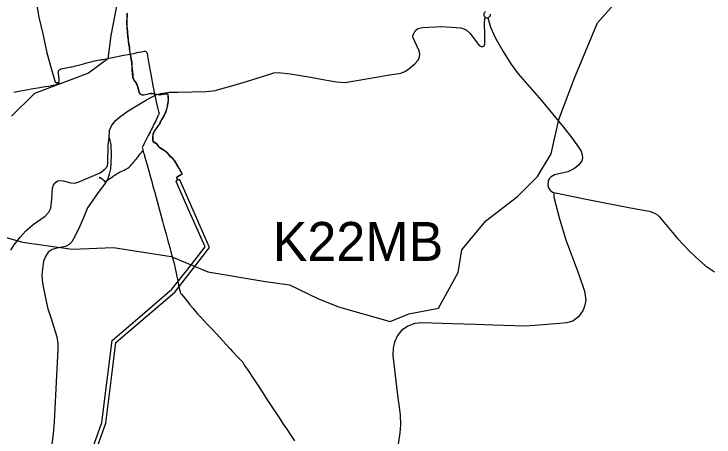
# Model space of a CAD drawing. Extents: x -789162 to -606354, y -1062736 to -945481.
# Drawn here: x -681766 to -679066, y -983825 to -982196 of the extents above; entities that cross this region are included whole.
import ezdxf

# ---------------------------------------------------------------- set-up
doc = ezdxf.new("R2010")
doc.units = 0
for name, color, linetype in [('_SIRSI VZTAHY_ELEKTRICKE VEDENI VN 110 kV S', 7, 'Continuous'), ('_SIRSI VZTAHY_SILNICE II TRIDY_STAV', 7, 'Continuous'), ('_SIRSI VZTAHY_SILNICE III TRIDY_STAV', 7, 'Continuous'), ('_SIRSI VZTAHY_USES_NRBK_S', 7, 'Continuous'), ('_SIRSI VZTAHY_USES_popis S', 7, 'Continuous'), ('_SIRSI VZTAHY_VTL PLYNOVOD', 7, 'Continuous')]:
    doc.layers.add(name, color=color, linetype=linetype)

msp = doc.modelspace()

# ---------------------------------------------------------------- linework, layer by layer
at = {"layer": '_SIRSI VZTAHY_ELEKTRICKE VEDENI VN 110 kV S'}
for points in [[(-681330.9, -982192.8), (-681331.2, -982203), (-681331.4, -982213.9), (-681331.8, -982221.6), (-681331.7, -982230.3), (-681331.6, -982234.4), (-681331.7, -982237.4), (-681331.5, -982240.2), (-681330.7, -982252.4), (-681329.8, -982263.2), (-681329.1, -982271.3), (-681328.4, -982276.7), (-681328.1, -982281.6), (-681327.8, -982283.8), (-681327, -982290.1)], [(-681329.9, -982192.7), (-681330.2, -982203), (-681330.5, -982213.9), (-681330.8, -982221.5), (-681330.7, -982230.5), (-681330.6, -982234.4), (-681330.7, -982237.1), (-681330.6, -982240.2), (-681329.8, -982252.2), (-681328.8, -982263.2), (-681328.1, -982271.4), (-681327.5, -982276.5), (-681327.2, -982281.6), (-681327, -982283.7), (-681326.2, -982290)], [(-681327, -982290.1), (-681326.9, -982291.3)], [(-681326.9, -982291.3), (-681326.2, -982296.7), (-681325.3, -982303.8), (-681323, -982317.6), (-681322, -982324.6), (-681321.5, -982328.9), (-681320.7, -982338), (-681319.9, -982343.9), (-681318.4, -982354.3), (-681316.7, -982362.4), (-681314.1, -982375.5), (-681312.9, -982380.1), (-681312.5, -982384.7), (-681312.1, -982398.7), (-681311.1, -982410.8), (-681309.9, -982424.4), (-681308.4, -982438.8), (-681307.7, -982442.3), (-681306.3, -982445.4), (-681303.7, -982450.8), (-681301.7, -982453.9), (-681299.6, -982455.1), (-681297.7, -982456.7), (-681296.3, -982460.1), (-681291.9, -982469.5), (-681290.7, -982472.7), (-681285.6, -982492.9), (-681284.6, -982497), (-681282.4, -982501.1), (-681279.7, -982504.4), (-681275.9, -982505.9), (-681271.6, -982506.7), (-681265.2, -982507.1), (-681258.7, -982506.1), (-681252.1, -982504.6), (-681242.9, -982502.2), (-681238.2, -982501.4), (-681235.1, -982501.6), (-681221.2, -982503.7), (-681205, -982506.9), (-681203.5, -982507), (-681202.2, -982506.8), (-681197, -982505.2), (-681192.2, -982504.2), (-681189.1, -982503.8), (-681184.6, -982503.3), (-681182.1, -982503.1), (-681179.1, -982503.2), (-681174.6, -982503.7), (-681173.2, -982505), (-681172.9, -982506.5), (-681173, -982509.6), (-681172.9, -982513.8), (-681172.3, -982518), (-681171.9, -982522.1), (-681171.9, -982525.8), (-681172.3, -982531.4), (-681172.8, -982534.8), (-681173.9, -982540.3), (-681175, -982546.7), (-681177.2, -982559), (-681178.6, -982564.3), (-681180.1, -982569.3), (-681183.2, -982576.6), (-681187.4, -982585.8), (-681191.2, -982592.3), (-681193.9, -982596.1), (-681201.6, -982609.8), (-681203.2, -982613.8), (-681203.9, -982615.9), (-681205.4, -982618.1), (-681208, -982622), (-681211.2, -982626.8), (-681213.1, -982629.5), (-681216.7, -982634.5), (-681222.1, -982641.6), (-681224.7, -982645.7), (-681227, -982649.7), (-681229.2, -982654.6), (-681230.2, -982658.9), (-681231.1, -982663.8), (-681231.7, -982668.9), (-681231.7, -982673.1), (-681231.8, -982677.3), (-681231.3, -982684), (-681231.1, -982684.8), (-681230.2, -982686.4), (-681220.1, -982692.8), (-681218.1, -982694.1), (-681216.4, -982696), (-681212, -982702.3), (-681208.7, -982706.5), (-681207.1, -982708.1), (-681205.5, -982709.3), (-681192.8, -982717.6), (-681187.8, -982720.7), (-681183.9, -982723.1), (-681181.8, -982724.7), (-681179.9, -982726.4), (-681174.9, -982731.5), (-681165.7, -982741.5), (-681158.7, -982748.9), (-681155, -982752.6), (-681151.8, -982755.9), (-681149.2, -982758.8), (-681147.1, -982761.9), (-681143.3, -982768.8), (-681136.3, -982780.7), (-681129.5, -982792.1), (-681124.7, -982800.2), (-681120.3, -982807.4), (-681119.2, -982809.1), (-681119, -982811.2), (-681120.1, -982813.2), (-681121.6, -982814.4), (-681135.4, -982822.1), (-681137.1, -982823), (-681138.8, -982824.8), (-681139.1, -982826.7), (-681138.5, -982828.2), (-681137.5, -982830.3), (-681136.9, -982831.6)], [(-681326.2, -982290), (-681326, -982291.2)], [(-681326, -982291.2), (-681325.4, -982296.7), (-681325.2, -982297.8), (-681324.4, -982303.7), (-681321.1, -982324.8), (-681320.1, -982334.7), (-681319.2, -982344), (-681317, -982356.2), (-681314.8, -982367.6), (-681313.2, -982375.5), (-681312.2, -982380), (-681311.9, -982384.5), (-681311.3, -982396.1), (-681310.8, -982404.3), (-681309.5, -982417.2), (-681308.3, -982429), (-681307.6, -982438.6), (-681306.9, -982442), (-681305.5, -982445.1), (-681302.9, -982450.5), (-681301.1, -982453.3), (-681298.9, -982454.6), (-681296.9, -982456.2), (-681295.5, -982459.8), (-681291, -982469.1), (-681289.6, -982472.4), (-681285, -982492.7), (-681283.8, -982496.7), (-681281.7, -982500.7), (-681279.3, -982504), (-681275.9, -982505.3), (-681271.6, -982505.9), (-681265.3, -982506.4), (-681258.9, -982505.4), (-681252.3, -982503.9), (-681243, -982501.6), (-681238.3, -982500.6), (-681234.9, -982501), (-681221, -982502.9), (-681204.7, -982506.1), (-681203.7, -982506.2), (-681202.2, -982505.8), (-681197.2, -982504.5), (-681192.3, -982503.5), (-681189.2, -982503.1), (-681184.6, -982502.6), (-681182.2, -982502.4), (-681179.1, -982502.6), (-681174.4, -982502.8), (-681173.3, -982503.5), (-681172.7, -982504.5), (-681172.7, -982505.3), (-681172.5, -982507.1), (-681172.2, -982509.6), (-681172, -982513.6), (-681171.4, -982518), (-681170.9, -982522.1), (-681171.1, -982525.8), (-681171.6, -982531.2), (-681172.2, -982535.6), (-681173.2, -982541.6), (-681173.7, -982544.8), (-681174.5, -982549), (-681176.1, -982557.6), (-681177.3, -982563.7), (-681178.9, -982568.9), (-681180.5, -982573.2), (-681183, -982578.7), (-681185.3, -982583.8), (-681186.9, -982586.9), (-681188.7, -982589.8), (-681190.8, -982593.2), (-681193.2, -982597.4), (-681200.9, -982610.3), (-681201.8, -982612.7), (-681202.9, -982615.4), (-681204.9, -982618.9), (-681208.4, -982624.3), (-681211.8, -982629.2), (-681216.1, -982635.3), (-681221.1, -982641.9), (-681223.9, -982646.1), (-681226.3, -982650.4), (-681228.4, -982654.8), (-681229.3, -982659), (-681230.3, -982664), (-681230.8, -982668.9), (-681230.8, -982673), (-681230.9, -982677.3), (-681230.6, -982683.9), (-681230.4, -982684.7), (-681229.8, -982685.6), (-681219.7, -982692.1), (-681217.5, -982693.4), (-681215.5, -982695.5), (-681211.2, -982701.6), (-681208, -982705.9), (-681206.5, -982707.3), (-681204.9, -982708.5), (-681192.2, -982716.6), (-681187.3, -982720), (-681183.3, -982722.4), (-681181.2, -982723.8), (-681179.5, -982725.5), (-681174.1, -982731), (-681162.1, -982743.8), (-681156.1, -982750.3), (-681150.4, -982755.9), (-681148.4, -982758.2), (-681146.1, -982761.8), (-681139.3, -982773.4), (-681133.3, -982783.7), (-681128.7, -982791.5), (-681124, -982799.6), (-681119.5, -982807.1), (-681118.7, -982808.6), (-681118.2, -982811.4), (-681119.3, -982813.8), (-681121.2, -982815.1), (-681134.8, -982822.8), (-681136.4, -982823.6), (-681137.9, -982825.1), (-681138.3, -982826.2), (-681138.2, -982827.2), (-681137, -982830), (-681136.2, -982831.4)], [(-680994.4, -985207.4), (-680997.7, -984992), (-681048.1, -984832), (-681140, -984667.6), (-681247.9, -984474.3), (-681337.5, -984313.8), (-681445.5, -984120.7), (-681493.2, -983954), (-681426.7, -983769.1), (-681404.1, -983585.5), (-681387.9, -983453.1), (-681261.4, -983345.4), (-681157.2, -983256.3), (-681091, -983172.1), (-681028.9, -983092.6), (-681088.7, -982957.8), (-681140.5, -982841), (-681135.7, -982834), (-681135.8, -982833.3), (-681136.9, -982831.6)], [(-680979.5, -985202.7), (-680982.8, -984989.6), (-681034.2, -984826.1), (-681126.9, -984660.3), (-681234.8, -984467), (-681324.4, -984306.5), (-681431.5, -984114.9), (-681477.4, -983954.5), (-681412, -983772.6), (-681389.2, -983587.3), (-681373.7, -983460.7), (-681251.7, -983356.8), (-681146.3, -983266.8), (-681079.2, -983181.3), (-681011.5, -983094.7), (-681075, -982951.7), (-681126.8, -982835), (-681135.3, -982833.8), (-681135.6, -982833.4), (-681136.2, -982831.4)]]:
    msp.add_lwpolyline(points, dxfattribs=at)
at = {"layer": '_SIRSI VZTAHY_SILNICE II TRIDY_STAV'}
for points in [[(-679947.4, -982185.9), (-679949.1, -982187), (-679950.7, -982188.5), (-679952, -982190.1), (-679953, -982192), (-679953.7, -982193.9), (-679954, -982196), (-679954, -982198.1), (-679953.7, -982200.2), (-679953.1, -982202.2), (-679952.1, -982204), (-679950.8, -982205.7), (-679949.3, -982207.1), (-679947.6, -982208.3)], [(-679938.4, -982209.7), (-679936.4, -982209.1), (-679934.5, -982208.1), (-679932.8, -982206.9), (-679931.3, -982205.4), (-679930.1, -982203.6), (-679929.2, -982201.7), (-679928.6, -982199.7), (-679928.4, -982197.6), (-679928.5, -982195.5)], [(-679947.6, -982208.3), (-679945.9, -982209.1), (-679944.1, -982209.7), (-679942.2, -982210), (-679940.3, -982210), (-679938.4, -982209.7)], [(-679938.4, -982209.7), (-679927.7, -982246.8), (-679908.4, -982288.1), (-679879.8, -982340.5), (-679850.4, -982387.6), (-679820.9, -982426.2), (-679731.2, -982529.2), (-679646.5, -982631.2), (-679614.4, -982672.8), (-679589.3, -982708.5), (-679578.7, -982724.4), (-679574.6, -982737.6), (-679573.7, -982749.8), (-679576.3, -982760.6), (-679582.1, -982770.7), (-679590.1, -982779.7), (-679604, -982790.6), (-679614.7, -982796.3), (-679630, -982803.5), (-679681.9, -982815.1), (-679694.6, -982822.5), (-679701.5, -982830.7), (-679705.7, -982840), (-679707.4, -982851.9), (-679706, -982861.4), (-679703.3, -982867.8), (-679698, -982874.7), (-679689, -982881.6), (-679684, -982883)], [(-679684, -982883), (-679559.6, -982908.9), (-679388.4, -982942.7), (-679316.8, -982955.6), (-679304.3, -982958.9), (-679292.8, -982963.8), (-679284, -982969.9), (-679277.1, -982976.3), (-679207.1, -983060.5), (-679161.2, -983109.3), (-679138.2, -983130.8), (-679098.5, -983165.2), (-679083.3, -983176.3), (-679064.1, -983188.7)]]:
    msp.add_lwpolyline(points, dxfattribs=at)
at = {"layer": '_SIRSI VZTAHY_SILNICE III TRIDY_STAV'}
for points in [[(-681398.6, -982671.1), (-681397.3, -982644.8), (-681389.9, -982625.8), (-681376.1, -982606.9), (-681359.2, -982592.8), (-681325.8, -982569.1), (-681255, -982526.8), (-681219, -982506.9), (-681199.6, -982501.9), (-681166.2, -982496.1), (-681134.6, -982496.9), (-681024.4, -982494.3), (-680988.6, -982490.4), (-680968.4, -982484.1), (-680916.8, -982469.1), (-680852.6, -982450.3), (-680775.8, -982425.4), (-680764.4, -982421.9), (-680746.6, -982420.5), (-680699.6, -982426), (-680622.5, -982438.8), (-680552.6, -982451.7), (-680522.4, -982457.1), (-680489.1, -982458.9), (-680406.3, -982445.3), (-680353.8, -982436.1), (-680341.6, -982434), (-680273.5, -982422.8), (-680259.2, -982417.4), (-680248.7, -982410.7), (-680220.2, -982387.3), (-680207.5, -982373.3), (-680201.7, -982360.9), (-680200.8, -982350.1), (-680202.8, -982337.1), (-680226.1, -982287.6), (-680227.5, -982279.7), (-680224.1, -982270.5), (-680218.8, -982260.2), (-680208.3, -982251.7), (-680190.2, -982247.2), (-680115.5, -982243.9), (-680060.8, -982247.4), (-680042.4, -982248.9), (-680031.1, -982252.7), (-680021.1, -982258.3), (-680007.4, -982269.8), (-679978.5, -982307.9), (-679972.5, -982316.5), (-679964.2, -982321.2), (-679957.6, -982320.6), (-679952.2, -982318), (-679950.3, -982311.1), (-679949.8, -982276.9), (-679951.3, -982230.2), (-679950.5, -982214.3), (-679947.6, -982208.3)], [(-681778.4, -983104.8), (-681765.3, -983085.5), (-681741.5, -983054.3), (-681720.1, -983030.6), (-681691.8, -983006.4), (-681646, -982974), (-681631.3, -982958.8), (-681624, -982943.4), (-681619.8, -982909.4), (-681619.1, -982888.3), (-681617.5, -982865.4), (-681613.7, -982855.2), (-681605.8, -982844.6), (-681596.6, -982838.3), (-681587.9, -982836.8), (-681576.9, -982838.2), (-681546.8, -982845.9), (-681533, -982846.7), (-681518.1, -982843.5), (-681501, -982836.2), (-681434.2, -982807), (-681415.1, -982793.8), (-681405.9, -982781.6), (-681404.5, -982768), (-681402.5, -982701.5), (-681398.6, -982671.1)], [(-681398.6, -982671.1), (-681392.2, -982699.2), (-681391.9, -982741.7), (-681393.6, -982792.6), (-681398.4, -982813.2), (-681404, -982830.9), (-681414.2, -982847.2), (-681444.1, -982887.2), (-681483.2, -982942), (-681499.8, -982983.9), (-681512.2, -983013.1), (-681531.5, -983052.2), (-681542.9, -983072.9), (-681553.6, -983083.2), (-681567.1, -983091.8), (-681600.6, -983097.4), (-681618.7, -983102.8), (-681634.9, -983113.5), (-681645, -983129.8), (-681652.1, -983148), (-681657.9, -983188.5), (-681659.1, -983201.7), (-681656.6, -983232.2), (-681642, -983302.3), (-681635.1, -983332.1), (-681624.4, -983364.9), (-681601.3, -983439), (-681597, -983464.6), (-681596.9, -983488.6), (-681602.3, -983588.9), (-681611.2, -983766.2), (-681615.2, -983814.6), (-681619.8, -983851.3)], [(-679684, -982883), (-679684, -982900.8), (-679662.6, -982984.1), (-679637.6, -983065.1), (-679587.3, -983198.9), (-679565.7, -983263.1), (-679561, -983296.9), (-679564.1, -983317.1), (-679570.8, -983336.6), (-679589.1, -983362), (-679610.6, -983378.6), (-679635.6, -983385), (-679661.7, -983388.3), (-679757.8, -983396.1), (-679794.6, -983397.7), (-679919.7, -983393.8), (-679985.5, -983391.8), (-680075.2, -983389.3), (-680193.9, -983385.8), (-680219.8, -983388.3), (-680246.7, -983398), (-680271.8, -983415.3), (-680286.9, -983434.4), (-680298.9, -983459.6), (-680304.2, -983483.2), (-680304.4, -983511.1), (-680287.7, -983653.4), (-680277.2, -983739.6), (-680275.4, -983778.1), (-680278.3, -983809.8), (-680303.8, -983983.8)]]:
    msp.add_lwpolyline(points, dxfattribs=at)
at = {"layer": '_SIRSI VZTAHY_USES_NRBK_S'}
for points in [[(-681879.6, -982004.1), (-681624.2, -981966.8), (-681508.9, -981972.9), (-681384.5, -982006.3), (-681352.7, -982070.1), (-681392.1, -982278.1), (-681404.2, -982367.7), (-681478.6, -982423.9), (-681686.5, -982501.3), (-681776, -982589.4)], [(-681873.1, -983034.2), (-681733.1, -983074.5), (-681541.9, -983101), (-681382.6, -983095.7), (-681159.6, -983130.3), (-681018.9, -983188.7), (-680795.8, -983225.9), (-680702.9, -983239.2), (-680594, -983292.3), (-680514.4, -983324.2), (-680315.2, -983380), (-680243.5, -983350.8), (-680129.4, -983329.5), (-680052.4, -983191.4), (-680039.1, -983103.7), (-679946.2, -982992.1), (-679824, -982899.1), (-679747, -982822), (-679693.9, -982734.4), (-679664.7, -982601.5), (-679603.6, -982439.4), (-679516, -982229.5), (-679441.7, -982147.2)]]:
    msp.add_lwpolyline(points, dxfattribs=at)
at = {"layer": '_SIRSI VZTAHY_VTL PLYNOVOD'}
for points in [[(-681681.9, -982139), (-681669.8, -982208.1), (-681655.5, -982272.3), (-681639.6, -982344.6), (-681624.1, -982399.9), (-681607.1, -982457.6), (-681603.5, -982458.9), (-681599.6, -982460), (-681598.9, -982460.2), (-681598.8, -982460.2), (-681599, -982461.1), (-681598.8, -982461.2), (-681598.7, -982461.2)], [(-681534, -982397.1), (-681507.5, -982390.5), (-681501.3, -982388.8), (-681484.9, -982384.1), (-681464.8, -982378.5), (-681460.3, -982377.5), (-681442.9, -982373.8), (-681431.2, -982371.8), (-681427.3, -982371.2), (-681422.5, -982370.4), (-681405.3, -982367.5), (-681386.5, -982363.4), (-681349.4, -982356), (-681335.4, -982353.4), (-681317.2, -982349.8), (-681300.3, -982345.9), (-681286.5, -982343.1), (-681274.8, -982340.8), (-681264.4, -982338.7), (-681261.2, -982338.5), (-681257.7, -982339.9), (-681255.2, -982341.9), (-681254.1, -982343.6), (-681253.1, -982347.2), (-681251.6, -982356.8), (-681245.8, -982387.1), (-681239.4, -982420.5), (-681233.9, -982449.7), (-681231.5, -982464.2), (-681229.1, -982477), (-681226.9, -982490.4), (-681225.4, -982501.6), (-681221.7, -982514.5), (-681220.6, -982520.6), (-681217.2, -982533.8), (-681212, -982555.1), (-681208.2, -982570.8), (-681206.4, -982578.6), (-681209.1, -982584.1), (-681209.6, -982585.5), (-681219.6, -982606.7), (-681226.2, -982620.5), (-681231.1, -982630.6), (-681232.6, -982633.6), (-681234.4, -982636.8), (-681234.8, -982637.7), (-681237, -982642), (-681237.3, -982642.7), (-681238.1, -982644.2), (-681240.8, -982649.5), (-681241.1, -982650.3), (-681248, -982664.1), (-681262.2, -982692.1), (-681265.4, -982698.3), (-681267.3, -982701.7), (-681269.2, -982705.3), (-681271.1, -982710.3), (-681271, -982712.1), (-681269.6, -982718), (-681269.4, -982718.9), (-681268.7, -982721.9), (-681268.7, -982722.1)], [(-681595.3, -982462.2), (-681595.2, -982462.2), (-681593.6, -982462.5), (-681592.4, -982462.6), (-681591.7, -982462), (-681591.6, -982459.9), (-681592.5, -982449.3), (-681593.7, -982434.8), (-681594.1, -982425.8), (-681594.2, -982420.1), (-681593.9, -982414.7), (-681589.2, -982408.9), (-681584.1, -982406.9), (-681571.3, -982404.6), (-681558.7, -982402), (-681545, -982399.2), (-681542.8, -982398.8), (-681535.8, -982397.5), (-681534, -982397.1)], [(-681534, -982397.1), (-681533.8, -982397.7)], [(-681597.2, -982463.1), (-681597.6, -982464), (-681598.3, -982465.3), (-681600.3, -982467.3), (-681601.7, -982468.2), (-681603, -982468.7), (-681608.7, -982469.6), (-681621.3, -982472), (-681632.9, -982474.2), (-681645.4, -982476.5), (-681665.8, -982479.9), (-681700.4, -982485.6), (-681710.9, -982487.5), (-681711.2, -982487.6), (-681740.4, -982493.1), (-681767.2, -982498.1)], [(-681597.3, -982463.1), (-681599, -982462.6), (-681598.9, -982462.3), (-681598.8, -982461.9)], [(-681598.8, -982461.9), (-681598.7, -982461.2)], [(-681597.6, -982462.3), (-681598.2, -982462.1), (-681598.8, -982461.9)], [(-681598.7, -982461.2), (-681598, -982461.4)], [(-681597.2, -982460.9), (-681597.8, -982460.7), (-681597.9, -982461.1), (-681598, -982461.4)], [(-681598, -982461.4), (-681597.4, -982461.6)], [(-681597.4, -982461.6), (-681597.6, -982462.3)], [(-681597.1, -982462.4), (-681597.6, -982462.3)], [(-681597.2, -982460.9), (-681597.3, -982461.3), (-681597.4, -982461.6)], [(-681597.4, -982461.6), (-681596.7, -982461.8), (-681595.8, -982462)], [(-681597.3, -982463.1), (-681597.3, -982462.8), (-681597.2, -982462.6), (-681597.1, -982462.4)], [(-681597.2, -982463.1), (-681597.3, -982463.1)], [(-681595.8, -982462), (-681595.8, -982461.7), (-681595.7, -982461.3), (-681596.8, -982461), (-681597.2, -982460.9)], [(-681597.2, -982463.1), (-681595.7, -982463.6), (-681595.6, -982463.2), (-681595.5, -982462.9)], [(-681595.5, -982462.9), (-681596.3, -982462.6), (-681597.1, -982462.4)], [(-681595.8, -982462), (-681595.3, -982462.2)], [(-681595.5, -982462.9), (-681595.3, -982462.2)], [(-681434.8, -982826.1), (-681434.6, -982826), (-681433.8, -982825.6), (-681433.3, -982825.4), (-681432.7, -982825.2), (-681432.3, -982825.2), (-681432, -982825.4), (-681423.3, -982833.7), (-681419.9, -982837.2), (-681419.8, -982837.3), (-681419.6, -982837.4), (-681416.5, -982840.5), (-681416.4, -982840.6), (-681415.9, -982840.9), (-681415.6, -982841.2), (-681415.2, -982841), (-681414.8, -982840.8), (-681382.4, -982819.7), (-681382.2, -982819.6), (-681377.8, -982816.3), (-681377.5, -982816.1), (-681377.3, -982815.9), (-681368.4, -982810.5), (-681368.1, -982810.5), (-681365.2, -982808.8), (-681358.7, -982805.1), (-681352.8, -982802.1), (-681348.2, -982799.7), (-681341.5, -982796.6), (-681337.1, -982794.4), (-681331.6, -982791.6), (-681326.3, -982788.9), (-681326, -982788.8), (-681325.7, -982788.6), (-681322.1, -982785.2), (-681317.2, -982780.2), (-681312.3, -982774.8), (-681309, -982770.9), (-681305.4, -982766.7), (-681301.5, -982762.3), (-681297.7, -982757.9), (-681293.6, -982752.9), (-681290.1, -982748.6), (-681286.1, -982743.4), (-681283, -982739.3), (-681278.9, -982733.8), (-681274.9, -982728.7), (-681271.3, -982724.2), (-681270.6, -982723.4), (-681270.3, -982723), (-681270, -982722.9), (-681269.4, -982722.7), (-681269.2, -982722.6), (-681269, -982722.5)], [(-681269, -982722.5), (-681269.1, -982722.2), (-681268.9, -982722.2), (-681268.7, -982722.1)], [(-681269, -982722.5), (-681268.8, -982722.5), (-681268.6, -982722.4)], [(-681268.7, -982722.1), (-681268.6, -982722.4)], [(-681268.6, -982722.4), (-681268.6, -982722.6), (-681268.1, -982724.6), (-681267.4, -982728.1), (-681265.2, -982732.5), (-681264.3, -982734.7), (-681263.6, -982736.3), (-681262.9, -982741.1), (-681262.7, -982741.9), (-681262.3, -982743.3), (-681253.6, -982773.3), (-681248.8, -982790.7), (-681245, -982804.3), (-681239.3, -982823.9), (-681234.9, -982841), (-681230, -982858.6), (-681223.4, -982883.5), (-681214.4, -982916.8), (-681206.3, -982945.7), (-681198.2, -982974.6), (-681192.9, -982994.2), (-681189.1, -983009.5), (-681184.4, -983026.3), (-681179.7, -983043.9), (-681172.4, -983069.6), (-681165.3, -983095.4), (-681158.1, -983122.6), (-681153.6, -983139.3), (-681151.3, -983148), (-681146.1, -983169.5), (-681140.6, -983193.7), (-681135.2, -983218.8), (-681130.2, -983246.3), (-681125.5, -983265.4), (-681123.3, -983271.3), (-681120.1, -983275), (-681113.6, -983283), (-681097.4, -983303.3), (-681087.4, -983315.8), (-681076.1, -983329.4), (-681064.3, -983343.4), (-681057.7, -983350.5), (-681047.4, -983361.4), (-681034.6, -983374.9), (-681018.2, -983392.7), (-681003.9, -983407.5), (-680986.4, -983426.2), (-680971.1, -983443.4), (-680946.3, -983470.2), (-680930.9, -983486.9), (-680924.3, -983494.3), (-680919.2, -983499.9), (-680906.1, -983513.7), (-680894.6, -983525.7), (-680885.1, -983536.1), (-680873.9, -983553.5), (-680863.3, -983569.2), (-680845.8, -983595.1), (-680831, -983618.1), (-680806.7, -983655.1), (-680789.1, -983681.7), (-680771.2, -983708.8), (-680752.6, -983736.9), (-680739.2, -983757.2), (-680727.3, -983776), (-680713.6, -983795.5), (-680697.3, -983820.5), (-680683.9, -983839.9)], [(-681435.5, -982826.4), (-681435.8, -982825.7), (-681436.1, -982824.9), (-681435.9, -982824.9), (-681435.7, -982824.8), (-681435.4, -982824.6), (-681435.2, -982825.2)], [(-681435.2, -982825.2), (-681435, -982825.1), (-681434.8, -982825)], [(-681435.2, -982825.2), (-681435.1, -982825.4), (-681434.8, -982826.1)], [(-681437.4, -982827.1), (-681437, -982827), (-681436.8, -982826.9), (-681436.7, -982826.9), (-681436.7, -982826.9), (-681436.6, -982826.8), (-681436.1, -982826.6), (-681435.7, -982826.5), (-681435.5, -982826.4)], [(-681435.5, -982826.4), (-681435.2, -982826.3), (-681434.8, -982826.1)]]:
    msp.add_lwpolyline(points, dxfattribs=at)

# ---------------------------------------------------------------- texts
at = {"layer": '_SIRSI VZTAHY_USES_popis S'}
msp.add_text('K22MB', height=150, dxfattribs=at).set_placement((-680768.2, -983146.8))

doc.saveas('drawing.dxf')
